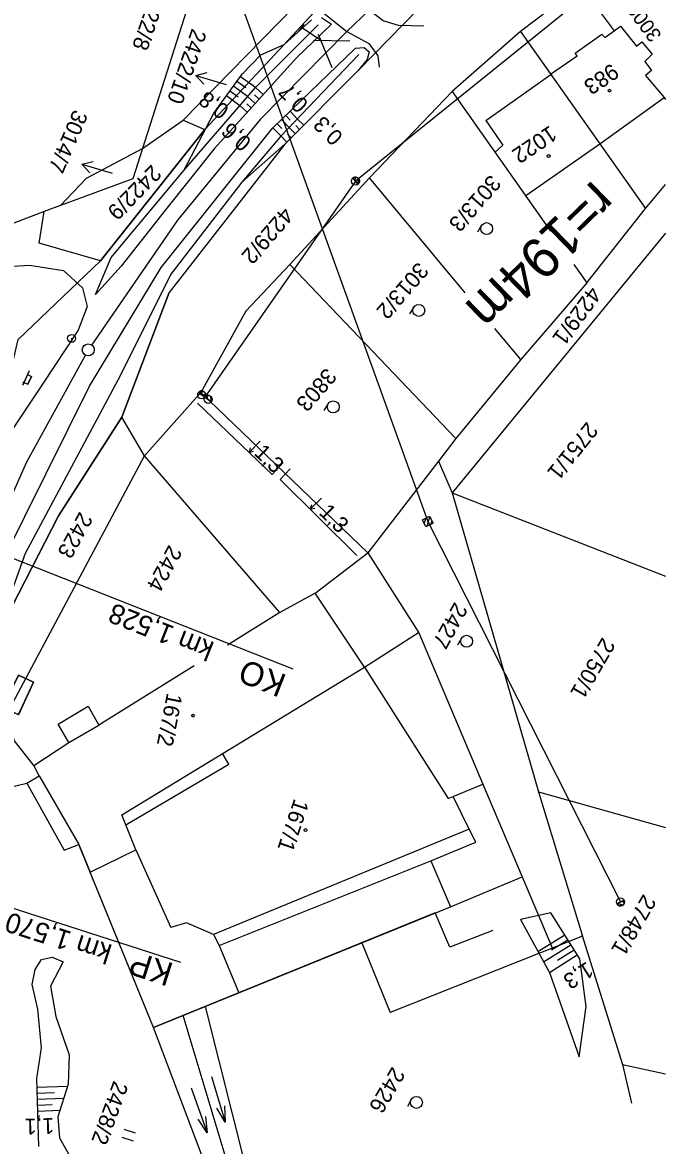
# Model space of a CAD drawing. Extents: x -659211 to -658900, y -1170600 to -1169973.
# Drawn here: x -658980.9 to -658900, y -1170267.3 to -1170126 of the extents above; entities that cross this region are included whole.
import ezdxf

# ---------------------------------------------------------------- set-up
doc = ezdxf.new("R2010")
doc.units = 0
for name, color, linetype in [('Vrstva 1', 7, 'Continuous'), ('Vrstva 13', 7, 'Continuous'), ('Vrstva 19', 7, 'Continuous'), ('Vrstva 23', 7, 'Continuous'), ('Vrstva 25', 7, 'Continuous'), ('Vrstva 36', 7, 'Continuous'), ('Vrstva 4', 7, 'Continuous'), ('Vrstva 47', 7, 'Continuous'), ('Vrstva 48', 7, 'Continuous'), ('Vrstva 49', 7, 'Continuous'), ('Vrstva 51', 7, 'Continuous'), ('Vrstva 53', 7, 'Continuous'), ('Vrstva 54', 7, 'Continuous'), ('Vrstva 55', 7, 'Continuous'), ('Vrstva 56', 7, 'Continuous'), ('Vrstva 57', 7, 'Continuous'), ('Vrstva 58', 7, 'Continuous'), ('Vrstva 59', 7, 'Continuous'), ('Vrstva 7', 7, 'Continuous')]:
    doc.layers.add(name, color=color, linetype=linetype)

msp = doc.modelspace()

# ---------------------------------------------------------------- linework, layer by layer
at = {"layer": 'Vrstva 1'}
for p, q in [((-658984.89, -1170192.35), (-658946.89, -1170207.35)), ((-658999.04, -1170232.01), (-658961.05, -1170244.24))]:
    msp.add_line(p, q, dxfattribs=at)
for points in [[(-658901.89, -1170098.72), (-658915.8, -1170107.44), (-658928.79, -1170117.11), (-658937.31, -1170124.47), (-658940.1, -1170127.18), (-658951, -1170138.22), (-658961.4, -1170150.9), (-658972.23, -1170166.62)], [(-658973.02, -1170167.91), (-658980.4, -1170181.35), (-658985.06, -1170191.75)]]:
    msp.add_lwpolyline(points, dxfattribs=at)
at = {"layer": 'Vrstva 13'}
for p, q in [((-658951.02, -1170178.69), (-658952.4, -1170180.13)), ((-658943.3, -1170185.86), (-658944.71, -1170187.28))]:
    msp.add_line(p, q, dxfattribs=at)
for points in [[(-658948.13, -1170181.39), (-658949.49, -1170182.91), (-658958.88, -1170173.93)], [(-658948.13, -1170181.39), (-658949.49, -1170182.91), (-658958.88, -1170173.93)], [(-658952.27, -1170179.56), (-658952.4, -1170180.13), (-658951.84, -1170179.98)], [(-658938.84, -1170193.09), (-658948.5, -1170183.52), (-658947.24, -1170182.17)], [(-658938.84, -1170193.09), (-658948.5, -1170183.52), (-658947.24, -1170182.17)], [(-658944.57, -1170186.72), (-658944.71, -1170187.28), (-658944.15, -1170187.14)]]:
    msp.add_lwpolyline(points, dxfattribs=at)
at = {"layer": 'Vrstva 19'}
for points in [[(-658980.07, -1170169.87), (-658980.89, -1170171.67)], [(-658980.07, -1170169.87), (-658980.3, -1170170.31), (-658980.28, -1170170.33), (-658980.73, -1170171.32), (-658980.82, -1170171.27), (-658980.89, -1170171.67)], [(-658980.73, -1170171.32), (-658980.23, -1170171.55)], [(-658980.28, -1170170.33), (-658979.78, -1170170.56)], [(-658979.79, -1170170.57), (-658979.78, -1170170.56), (-658980.23, -1170171.55), (-658980.23, -1170171.54), (-658979.79, -1170170.57)]]:
    msp.add_lwpolyline(points, dxfattribs=at)
at = {"layer": 'Vrstva 23'}
msp.add_lwpolyline([(-658921.73, -1170240.26), (-658927.15, -1170242.38), (-658928.99, -1170238.06), (-658964.45, -1170252.47), (-658973.83, -1170229.43)], dxfattribs=at)
at = {"layer": 'Vrstva 25'}
for points in [[(-658927.37, -1169973.42), (-658942.67, -1170043.74), (-658957.73, -1170111.71), (-658929.93, -1170188.82), (-658905.67, -1170236.68)], [(-658900, -1170116.02), (-658908.77, -1170121.59), (-658939.02, -1170145.99), (-658957.96, -1170173.16)]]:
    msp.add_lwpolyline(points, dxfattribs=at)
at = {"layer": 'Vrstva 36'}
for p, q in [((-658938.7, -1170146.38), (-658939.34, -1170145.59)), ((-658939.34, -1170145.59), (-658938.7, -1170146.38)), ((-658939.04, -1170145.49), (-658939.08, -1170145.91)), ((-658938.67, -1170145.62), (-658938.75, -1170146.32)), ((-658958.78, -1170172.59), (-658957.96, -1170173.16)), ((-658957.96, -1170173.16), (-658958.78, -1170172.59)), ((-658958.03, -1170172.5), (-658958.73, -1170172.63)), ((-658957.87, -1170172.85), (-658958.29, -1170172.93)), ((-658957.7, -1170172.98), (-658957.62, -1170173.4)), ((-658957.31, -1170173.01), (-658957.19, -1170173.7)), ((-658957.13, -1170173.74), (-658957.96, -1170173.16)), ((-658957.96, -1170173.16), (-658957.13, -1170173.74)), ((-658930.36, -1170189.09), (-658930.12, -1170188.35)), ((-658930.05, -1170189.44), (-658929.66, -1170188.25)), ((-658929.55, -1170189.19), (-658929.41, -1170188.76)), ((-658906.12, -1170236.9), (-658905.22, -1170236.45)), ((-658905.22, -1170236.45), (-658906.12, -1170236.9)), ((-658905.18, -1170236.76), (-658905.58, -1170236.63)), ((-658905.39, -1170237.09), (-658906.05, -1170236.87))]:
    msp.add_line(p, q, dxfattribs=at)
msp.add_lwpolyline([(-658930.6, -1170188.6), (-658929.71, -1170188.15), (-658929.26, -1170189.04), (-658930.15, -1170189.49), (-658930.6, -1170188.6)], dxfattribs=at)
for centre in [(-658939.02, -1170145.99), (-658958.37, -1170172.88), (-658957.54, -1170173.45), (-658905.67, -1170236.68)]:
    msp.add_circle(centre, 0.503, dxfattribs=at)
for centre, start, end in [((-658939.02, -1170145.99), 308.8865, 128.8865), ((-658958.37, -1170172.88), 325.1318, 145.1318), ((-658957.54, -1170173.45), 325.1318, 145.1318), ((-658905.67, -1170236.68), 206.8892, 26.8892)]:
    msp.add_arc(centre, 0.503, start, end, dxfattribs=at)
at = {"layer": 'Vrstva 4'}
for p, q in [((-658937.31, -1170124.47), (-658940.1, -1170127.18)), ((-658945.53, -1170126.23), (-658946.1, -1170127.06)), ((-658943.39, -1170128.31), (-658945.82, -1170126.64)), ((-658943.72, -1170127.48), (-658942, -1170131.69)), ((-658939.74, -1170128.39), (-658944.29, -1170128.3))]:
    msp.add_line(p, q, dxfattribs=at)
at = {"layer": 'Vrstva 47'}
for points in [[(-658983.38, -1170212.23), (-658981.44, -1170208.15), (-658979.53, -1170209.04), (-658981.42, -1170213.12), (-658983.38, -1170212.23)], [(-658981.44, -1170208.16), (-658983.37, -1170212.22), (-658981.42, -1170213.11), (-658979.54, -1170209.04), (-658981.44, -1170208.16)], [(-658979.53, -1170209.04), (-658979.54, -1170209.04)]]:
    msp.add_lwpolyline(points, dxfattribs=at)
at = {"layer": 'Vrstva 48'}
for p, q in [((-658952.83, -1170134.25), (-658953.93, -1170133.45)), ((-658951.61, -1170134.22), (-658953.48, -1170132.85)), ((-658953.78, -1170135.42), (-658954.81, -1170134.67)), ((-658952.59, -1170135.36), (-658954.37, -1170134.06)), ((-658951.61, -1170134.22), (-658950.63, -1170135.11)), ((-658953.58, -1170136.5), (-658955.25, -1170135.27)), ((-658952.7, -1170136.26), (-658952.14, -1170136.77)), ((-658952.59, -1170135.35), (-658951.63, -1170136.22)), ((-658951.71, -1170135.14), (-658951.13, -1170135.66)), ((-658953.57, -1170136.49), (-658952.64, -1170137.33)), ((-658947.23, -1170138.3), (-658947.79, -1170137.72)), ((-658946.34, -1170138.15), (-658947.25, -1170137.2)), ((-658948.29, -1170139.37), (-658948.87, -1170138.77)), ((-658947.38, -1170139.23), (-658948.33, -1170138.25)), ((-658946.54, -1170139.01), (-658946.06, -1170139.49)), ((-658946.34, -1170138.15), (-658945.53, -1170138.96)), ((-658948.42, -1170140.31), (-658949.41, -1170139.29)), ((-658948.42, -1170140.31), (-658947.64, -1170141.09)), ((-658947.58, -1170140.08), (-658947.11, -1170140.55)), ((-658947.38, -1170139.23), (-658946.58, -1170140.02)), ((-658916.05, -1170242.91), (-658912.69, -1170240.8)), ((-658915.34, -1170244.22), (-658911.9, -1170242.07)), ((-658914.33, -1170242.71), (-658912.3, -1170241.44)), ((-658914.62, -1170245.54), (-658911.1, -1170243.34)), ((-658913.59, -1170244.01), (-658911.5, -1170242.71)), ((-658975.24, -1170259.9), (-658979.08, -1170260.02)), ((-658976.91, -1170260.7), (-658979.06, -1170260.77)), ((-658975.72, -1170261.42), (-658979.03, -1170261.52)), ((-658977.18, -1170262.21), (-658979.01, -1170262.27)), ((-658976.2, -1170262.93), (-658978.99, -1170263.02))]:
    msp.add_line(p, q, dxfattribs=at)
at = {"layer": 'Vrstva 49'}
for p, q in [((-658951.6, -1170134.21), (-658943.73, -1170126.31)), ((-658948, -1170128.82), (-658944.57, -1170125.68)), ((-658942.02, -1170126.23), (-658946.44, -1170130.48)), ((-658943.3, -1170125.39), (-658942.02, -1170126.23)), ((-658950.91, -1170130.08), (-658948, -1170128.82)), ((-658949.41, -1170139.29), (-658939.03, -1170129.27)), ((-658939.03, -1170129.27), (-658937.94, -1170129.16)), ((-658937.94, -1170129.16), (-658937.31, -1170129.74)), ((-658946.44, -1170130.48), (-658956.79, -1170141.91)), ((-658953.27, -1170132.55), (-658950.91, -1170130.08)), ((-658938.58, -1170130.04), (-658948.46, -1170140.36)), ((-658937.54, -1170130.7), (-658938.69, -1170132.09)), ((-658937.31, -1170129.74), (-658937.54, -1170130.7)), ((-658938.69, -1170132.09), (-658947.9, -1170141.35)), ((-658956.84, -1170137.45), (-658953.27, -1170132.55)), ((-658960.61, -1170144.64), (-658951.6, -1170134.21)), ((-658960.61, -1170144.64), (-658956.84, -1170137.45)), ((-658963.47, -1170156.87), (-658949.41, -1170139.29)), ((-658948.46, -1170140.36), (-658953.31, -1170146.12)), ((-658956.79, -1170141.91), (-658962.94, -1170149.61)), ((-658947.9, -1170141.35), (-658953.31, -1170146.12)), ((-658969.76, -1170155.58), (-658960.61, -1170144.64)), ((-658953.31, -1170146.12), (-658962.27, -1170157.7)), ((-658962.94, -1170149.61), (-658968.49, -1170156.67)), ((-658971.75, -1170160.25), (-658969.76, -1170155.58)), ((-658985.29, -1170156.91), (-658980.03, -1170156.57)), ((-658980.03, -1170156.57), (-658975.75, -1170157.25)), ((-658975.75, -1170157.25), (-658973.38, -1170159.41)), ((-658972.5, -1170171.8), (-658963.47, -1170156.87)), ((-658968.49, -1170156.67), (-658971.75, -1170160.25)), ((-658962.27, -1170157.7), (-658968.59, -1170170.41)), ((-658973.38, -1170159.41), (-658972.78, -1170161.75)), ((-658972.78, -1170161.75), (-658973.9, -1170164.75)), ((-658973.9, -1170164.75), (-658978.38, -1170171.54)), ((-658978.38, -1170171.54), (-658982.94, -1170178.31)), ((-658968.59, -1170170.41), (-658980.6, -1170192.83)), ((-658983.39, -1170193.77), (-658972.5, -1170171.8)), ((-658980.6, -1170192.83), (-658987.94, -1170213.34)), ((-658914.43, -1170238.04), (-658918.25, -1170238.88)), ((-658910.79, -1170243.85), (-658914.43, -1170238.04)), ((-658918.25, -1170238.88), (-658914.61, -1170245.55)), ((-658978.51, -1170243.9), (-658977.19, -1170243.62)), ((-658977.19, -1170243.62), (-658975.78, -1170244.19)), ((-658979.7, -1170247.06), (-658979.33, -1170245.17)), ((-658979.33, -1170245.17), (-658978.51, -1170243.9)), ((-658975.78, -1170244.19), (-658977.38, -1170247.28)), ((-658910, -1170249.85), (-658910.79, -1170243.85)), ((-658914.61, -1170245.55), (-658910.86, -1170256.18)), ((-658978.99, -1170250.16), (-658979.7, -1170247.06)), ((-658977.38, -1170247.28), (-658976.71, -1170251.1)), ((-658978.52, -1170255.04), (-658978.99, -1170250.16)), ((-658910.86, -1170256.18), (-658910, -1170249.85)), ((-658976.71, -1170251.1), (-658975.04, -1170255.89)), ((-658979.11, -1170258.88), (-658978.52, -1170255.04)), ((-658975.04, -1170255.89), (-658975.15, -1170259.6)), ((-658978.86, -1170267.46), (-658979.11, -1170258.88)), ((-658975.15, -1170259.6), (-658976.45, -1170263.7)), ((-658976.45, -1170263.7), (-658976.27, -1170266.34)), ((-658976.27, -1170266.34), (-658975.07, -1170268.46))]:
    msp.add_line(p, q, dxfattribs=at)
at = {"layer": 'Vrstva 51'}
for points in [[(-658930.41, -1170126.49), (-658933.61, -1170126.42), (-658935.52, -1170125.81), (-658937.31, -1170124.47), (-658940.97, -1170122.06)], [(-658943, -1170124.87), (-658940.1, -1170127.18), (-658937.33, -1170128.67), (-658936.19, -1170130.21), (-658936.04, -1170131.66)]]:
    msp.add_lwpolyline(points, dxfattribs=at)
at = {"layer": 'Vrstva 53'}
for points in [[(-658971.09, -1170156.01), (-658957.97, -1170139.48), (-658948, -1170128.82), (-658940.95, -1170121.17), (-658938.24, -1170118.58), (-658927.08, -1170109.4), (-658906.04, -1170095.36), (-658900.02, -1170092.6)], [(-658900.01, -1170103.7), (-658911.5, -1170109.89), (-658922.98, -1170117.91), (-658930.99, -1170124.22), (-658938.69, -1170132.09), (-658947.9, -1170141.35), (-658962.46, -1170159.99)], [(-659002.13, -1170227.74), (-658997.95, -1170214.32), (-658994.54, -1170206.57), (-658991.53, -1170198.84), (-658984.58, -1170181.01), (-658984.14, -1170178.35), (-658983.04, -1170172.82), (-658981.46, -1170165.92), (-658971.09, -1170156.01)], [(-658962.46, -1170159.99), (-658968.43, -1170175.7), (-658976.4, -1170188.09), (-658983.99, -1170202.81), (-658991.44, -1170224.37), (-659014.8, -1170327)]]:
    msp.add_lwpolyline(points, dxfattribs=at)
at = {"layer": 'Vrstva 54'}
for p, q in [((-658959.1, -1170132.7), (-658955.28, -1170133.82)), ((-658973.47, -1170143.87), (-658969.65, -1170145))]:
    msp.add_line(p, q, dxfattribs=at)
for points in [[(-658958.08, -1170133.79), (-658959.1, -1170132.7), (-658957.67, -1170132.33)], [(-658972.45, -1170144.96), (-658973.47, -1170143.87), (-658972.03, -1170143.51)]]:
    msp.add_lwpolyline(points, dxfattribs=at)
at = {"layer": 'Vrstva 55'}
for p, q in [((-658910.7, -1170121.4), (-658906.47, -1170127.06)), ((-658960.69, -1170138.31), (-658946.72, -1170124.07)), ((-658918.27, -1170127.17), (-658902.52, -1170149.43)), ((-658900.18, -1170135.46), (-658900, -1170135.71)), ((-658902.52, -1170149.43), (-658900, -1170146.43)), ((-658965.56, -1170180.57), (-658965.56, -1170180.57)), ((-658926.84, -1170185.21), (-658916, -1170222.82)), ((-658948.52, -1170200.26), (-658955.13, -1170204.37)), ((-658959.31, -1170206.96), (-658971.31, -1170214.42))]:
    msp.add_line(p, q, dxfattribs=at)
for points in [[(-658911.5, -1170109.89), (-658922.98, -1170117.91), (-658930.99, -1170124.22), (-658938.69, -1170132.09), (-658947.9, -1170141.35), (-658962.46, -1170159.99)], [(-658944.3, -1170124.81), (-658946.72, -1170124.07), (-658958.77, -1170119.76), (-658965.8, -1170141.87), (-658967.03, -1170145.68), (-658976.15, -1170149.06), (-658978.17, -1170149.81), (-658989.34, -1170154.09), (-659004.05, -1170144.06), (-659024.08, -1170138.93)], [(-658940.95, -1170121.17), (-658944.3, -1170124.81), (-658948, -1170128.82), (-658957.97, -1170139.48), (-658971.09, -1170156.01), (-658978.83, -1170153.79), (-658978.17, -1170149.81)], [(-658910.7, -1170121.4), (-658918.27, -1170127.17), (-658926.84, -1170134.72), (-658914.46, -1170152.29)], [(-658906.47, -1170127.06), (-658905.65, -1170126.48), (-658903.65, -1170129.03), (-658902.99, -1170128.47), (-658901.7, -1170130.01), (-658902.62, -1170130.94), (-658901.75, -1170132.06), (-658902.53, -1170132.72), (-658900.18, -1170135.46)], [(-658947.26, -1170156.46), (-658937.27, -1170145.57), (-658926.84, -1170134.72)], [(-658965.8, -1170141.87), (-658960.69, -1170138.31), (-658957.97, -1170139.48)], [(-658976.15, -1170149.06), (-658972.86, -1170145.61), (-658965.8, -1170141.87)], [(-658925.2, -1170160.04), (-658937.27, -1170145.57)], [(-658911.53, -1170156.46), (-658909.89, -1170158.79), (-658902.52, -1170149.43)], [(-658900, -1170152.52), (-658926.84, -1170185.21)], [(-658984.58, -1170181.01), (-658984.14, -1170178.35), (-658983.04, -1170172.82), (-658981.46, -1170165.92), (-658971.09, -1170156.01)], [(-658918.19, -1170168.45), (-658926.4, -1170178.35), (-658947.26, -1170156.46), (-658952.81, -1170162.37), (-658958.48, -1170172.6)], [(-658909.89, -1170158.79), (-658918.19, -1170168.45), (-658921.46, -1170164.52)], [(-658991.44, -1170224.37), (-658983.99, -1170202.81), (-658976.4, -1170188.09), (-658968.43, -1170175.7), (-658962.46, -1170159.99)], [(-658965.56, -1170180.57), (-658958.48, -1170172.6), (-658937.46, -1170192.74)], [(-658979.5, -1170219.51), (-658981.93, -1170216.41), (-658982.81, -1170212.87), (-658965.56, -1170180.57), (-658968.43, -1170175.7)], [(-658926.4, -1170178.35), (-658928.58, -1170181.24), (-658926.84, -1170185.21)], [(-658964.45, -1170252.47), (-658972.39, -1170232.95), (-658966.64, -1170230.14), (-658968.43, -1170225.7), (-658937.9, -1170207.12), (-658944.1, -1170197.82), (-658948.52, -1170200.26), (-658965.56, -1170180.57)], [(-658928.58, -1170181.24), (-658937.46, -1170192.74), (-658931.06, -1170202.82), (-658923, -1170221.87), (-658918.05, -1170233.52), (-658914.23, -1170242.52)], [(-658926.84, -1170185.21), (-658900, -1170195.71)], [(-658991.44, -1170224.37), (-658980.38, -1170221.72), (-658978.83, -1170220.83), (-658979.5, -1170219.51), (-658975.07, -1170216.63), (-658976.43, -1170214.33), (-658972.64, -1170212.05), (-658971.31, -1170214.42)], [(-658980.38, -1170221.72), (-658975.67, -1170230.17), (-658973.83, -1170229.43), (-658972.39, -1170232.95)], [(-658916, -1170222.82), (-658910.47, -1170240.97), (-658934.65, -1170250.6)], [(-658916, -1170222.82), (-658900, -1170227.33)], [(-658910.52, -1170240.76), (-658905.4, -1170257.13), (-658900, -1170258.31)], [(-658917.65, -1170277.74), (-658918.62, -1170280.76), (-658955.16, -1170276.81), (-658958.43, -1170268.32), (-658964.45, -1170252.47), (-658938.23, -1170241.83), (-658934.65, -1170250.6)], [(-658904.88, -1170276.14), (-658916.05, -1170273.67), (-658916.29, -1170274.79), (-658949.49, -1170272.55), (-658952.77, -1170270.16), (-658957.89, -1170249.82)], [(-658916.29, -1170274.79), (-658917.65, -1170277.74), (-658949.1, -1170275.11), (-658952.21, -1170274.15), (-658953.94, -1170272.84), (-658954.67, -1170271.1), (-658960.68, -1170250.95)], [(-658905.4, -1170257.13), (-658904.27, -1170261.99)]]:
    msp.add_lwpolyline(points, dxfattribs=at)
at = {"layer": 'Vrstva 56'}
for p, q in [((-658954.95, -1170219.35), (-658955.75, -1170217.98)), ((-658927.36, -1170223.66), (-658926.71, -1170223.42)), ((-658924.7, -1170227.53), (-658926.71, -1170223.42)), ((-658927.08, -1170237.28), (-658918.05, -1170233.52))]:
    msp.add_line(p, q, dxfattribs=at)
for points in [[(-658911.37, -1170129.88), (-658908.02, -1170127.48)], [(-658908.02, -1170127.48), (-658907.66, -1170127.93), (-658906.47, -1170127.06)], [(-658914.49, -1170132.52), (-658911.11, -1170130.21), (-658911.37, -1170129.88)], [(-658922.61, -1170138.37), (-658914.44, -1170132.58)], [(-658908.27, -1170141.3), (-658900.18, -1170135.46)], [(-658922.61, -1170138.37), (-658920.47, -1170141.46), (-658921.46, -1170142.37)], [(-658917.56, -1170147.81), (-658908.27, -1170141.3)], [(-658944.1, -1170197.82), (-658937.46, -1170192.74)], [(-658937.9, -1170207.12), (-658931.08, -1170202.77)], [(-658937.9, -1170207.12), (-658927.36, -1170223.66)], [(-658975.07, -1170216.63), (-658971.31, -1170214.42)], [(-658967.91, -1170226.99), (-658954.95, -1170219.35)], [(-658978.83, -1170220.83), (-658973.83, -1170229.43)], [(-658926.71, -1170223.42), (-658923, -1170221.87)], [(-658929.54, -1170231.49), (-658923.89, -1170229.15), (-658924.7, -1170227.53), (-658956.87, -1170240.77), (-658956.15, -1170242.14)], [(-658966.64, -1170230.14), (-658962.27, -1170239.88)], [(-658956.15, -1170242.14), (-658929.54, -1170231.49)], [(-658929.54, -1170231.49), (-658927.08, -1170237.28)], [(-658938.23, -1170241.83), (-658927.08, -1170237.28)], [(-658956.87, -1170240.77), (-658960.26, -1170239.31), (-658962.27, -1170239.88)], [(-658956.15, -1170242.14), (-658953.71, -1170248.11)]]:
    msp.add_lwpolyline(points, dxfattribs=at)
at = {"layer": 'Vrstva 58'}
for p, q in [((-658923.14, -1170151.55), (-658923.68, -1170152.4)), ((-658931.68, -1170161.85), (-658932.22, -1170162.69)), ((-658942.46, -1170173.98), (-658942.99, -1170174.83)), ((-658925.69, -1170203.51), (-658926.18, -1170204.38)), ((-658957.14, -1170258.63), (-658955.4, -1170264.37)), ((-658959.68, -1170260.05), (-658957.69, -1170265.71)), ((-658932, -1170261.53), (-658932.49, -1170262.41)), ((-658968.42, -1170266.28), (-658966.99, -1170266.72)), ((-658966.69, -1170265.77), (-658968.13, -1170265.32))]:
    msp.add_line(p, q, dxfattribs=at)
for points in [[(-658955.5, -1170262.31), (-658955.4, -1170264.37), (-658956.46, -1170262.6)], [(-658957.88, -1170263.66), (-658957.69, -1170265.71), (-658958.82, -1170263.99)]]:
    msp.add_lwpolyline(points, dxfattribs=at)
for centre in [(-658922.51, -1170151.96), (-658931.05, -1170162.25), (-658941.82, -1170174.39), (-658925.04, -1170203.88), (-658931.34, -1170261.9)]:
    msp.add_circle(centre, 0.75, dxfattribs=at)
at = {"layer": 'Vrstva 59'}
for centre in [(-658907.05, -1170134.61), (-658914.71, -1170142.83), (-658959.46, -1170213.24), (-658945.3, -1170227.63)]:
    msp.add_circle(centre, 0.175, dxfattribs=at)
at = {"layer": 'Vrstva 7'}
msp.add_line((-658974.79, -1170165.77), (-658974.69, -1170165.77), dxfattribs=at)
for centre, radius in [((-658974.74, -1170165.77), 0.5), ((-658972.64, -1170167.22), 0.75)]:
    msp.add_circle(centre, radius, dxfattribs=at)

# ---------------------------------------------------------------- texts
at = {"layer": 'Vrstva 1'}
for s, height, rotation, p in [('r=194m', 5, 224.1449, (-658909.11, -1170145.72)), ('km 1,528', 2.5, 158.4626, (-658956.64, -1170204.07)), ('KO', 3, 158.4626, (-658947.52, -1170208.19)), ('km 1,570', 2.5, 162.1531, (-658969.48, -1170242.13)), ('KP', 3, 162.1531, (-658961.75, -1170244.47))]:
    msp.add_text(s, height=height, rotation=rotation, dxfattribs=at).set_placement(p)
at = {"layer": 'Vrstva 13'}
for rotation, p in [(316.26, (-658951.89, -1170180.32)), (315.2653, (-658943.72, -1170187.8))]:
    msp.add_text('1,3', height=2, rotation=rotation, dxfattribs=at).set_placement(p)
at = {"layer": 'Vrstva 48'}
for s, rotation, p in [('0,8', 143.9078, (-658954.76, -1170136.73)), ('0,7', 133.9483, (-658944.82, -1170136.2)), ('0,6', 137.8769, (-658951.97, -1170140.94)), ('0,3', 135.1761, (-658940.45, -1170140.27)), ('1,3', 212.0493, (-658909.9, -1170244.11)), ('1,1', 181.6859, (-658976.95, -1170263.85))]:
    msp.add_text(s, height=2, rotation=rotation, dxfattribs=at).set_placement(p)
at = {"layer": 'Vrstva 57'}
for s, height, rotation, p in [('2422/8', 2, 250.9805, (-658964.48, -1170121.36)), ('3009/2', 1.8, 126.2062, (-658900.41, -1170127.62)), ('2422/10', 2, 250.9623, (-658959.59, -1170126.68)), ('983', 2, 213.9919, (-658906.77, -1170131.09)), ('3014/7', 2, 246.4665, (-658974.45, -1170136.87)), ('1022', 2, 213.9919, (-658914.56, -1170138.91)), ('2422/9', 2, 225.542, (-658964.66, -1170143.81)), ('3013/3', 2, 229.0243, (-658922.04, -1170145.06)), ('4229/2', 2, 229.0243, (-658948.13, -1170149.12)), ('3013/2', 2, 229.0243, (-658931.15, -1170156.05)), ('4229/1', 2, 233.7247, (-658909.51, -1170159.09)), ('3803', 2, 229.0243, (-658942.72, -1170169.36)), ('2751/1', 2, 231.3813, (-658909.89, -1170176.16)), ('2423', 2, 241.2734, (-658973.72, -1170187.48)), ('2424', 2, 241.2734, (-658962.48, -1170191.65)), ('2427', 2, 241.2734, (-658926.54, -1170198.85)), ('2750/1', 2, 239.7136, (-658907.94, -1170203.28)), ('167/2', 2, 258.7981, (-658962.72, -1170210.3)), ('167/1', 2, 251.2985, (-658946.71, -1170223.59)), ('2748/1', 2, 239.7136, (-658902.78, -1170235.59)), ('2426', 2, 239.7136, (-658934.38, -1170257.3)), ('2428/2', 2, 249.6006, (-658969.43, -1170259.07))]:
    msp.add_text(s, height=height, rotation=rotation, dxfattribs=at).set_placement(p)

doc.saveas('drawing.dxf')
